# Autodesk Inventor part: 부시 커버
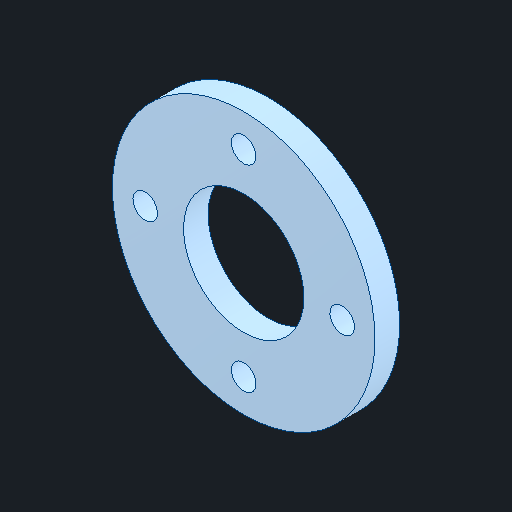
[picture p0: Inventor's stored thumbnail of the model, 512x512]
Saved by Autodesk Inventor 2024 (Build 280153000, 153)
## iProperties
Created: 2024-05
Part Number: 부시 커버
Material: 강철, 연강
Document SubType Name: Modeling
Designer: kh_501
Density: 7.85 g/cm^3
Appearance: 기본값
Author: jhkim
Sending System: Autodesk Inventor 2025
Preprocessor: ST-DEVELOPER v20
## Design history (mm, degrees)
feature "솔리드1"
node "솔리드2"
